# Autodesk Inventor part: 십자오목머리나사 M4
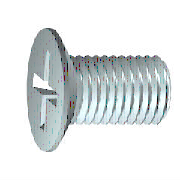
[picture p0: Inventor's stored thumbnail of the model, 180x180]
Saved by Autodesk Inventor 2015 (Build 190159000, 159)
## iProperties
IsCustomPart: 0
Created: 2012-02
Part Number: 십자오목머리나사 M4
Material: 강철, 연강
Description: 십자 오목 머리 나사
Document SubType Name: Modeling
Standard: KS B 1023
Designer: mduedu
Standards Organization: KS
Language: ko-KR
Size Designation: A  M 4 x 12 - H
Categories: <MemberInstance><Categories><Category DisplayName="조임쇠" InternalName="e4da775c-781d-43d5-af7c-5136215cf5a6" Mnemonic="FSTN"><Category DisplayName="볼트" InternalN
Density: 7.86 g/cm^3
Mass: 1.5048 g
Surface Area: 2.78557 cm^2
Volume: 0.191451 cm^3
Appearance: 주황색
Author: mduedu
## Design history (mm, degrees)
body "Solid1"
sketch "스케치1"
  geometry: L1 (2.6, 0)-(12, 0); L2 (12, 0)-(12, 2); L3 (12, 2)-(4.1, 2); L4 (4.1, 2)-(3.671, 1.785); L5 (3.671, 1.785)-(2.7, 1.785); L6 (0, 4.2)-(0, 2.4); L7 (0, 2.4)-(1.801, 1.502); L8 (1.801, 1.502)-(2.6, 0); L9 (-2.4, 0)-(14.4, 0) reference; L10 (0, -0.84)-(0, 5.04) reference; L11 (0, 4.2)-(0.285, 4.2); L12 (0.285, 4.2)-(2.7, 1.785); L13 (4.1, 2)-(2.485, 2)
  constraints: 22 end point, 3 parallel, 3 perpendicular, 2 collinear, 1 horizontal, 1 point on line
  dimensions: "d1" = 7.9 distance of L2.end L3.end (= GEL); "d2" = 4 diameter of L3 L1 (= GD); "d3" = 3.57058 diameter of L5 L1 (= BDM); "d4" = 4.8 diameter of L6.end L1 (= SDM); "d5" = 26.5 deg angle of L7 L1; "d6" = 62 deg angle of L8 L1; "d7" = 2.6 distance from line of L1.start L6 (= INTI); "d8" = 0.42941 horizontal distance of L4.end L3.end (= GAL); "d12" = 8.4 diameter of L11 L1 (= KOD); "d13" = 45 deg angle of L12 L1 (= 0.5 x SEWI); "d15" = 12 distance between parallel lines of L2 L6 (= NLG); "d24" = 2.7 distance from line of L5.end L6 (= KOH)
revolve "본체" stored, may be unused: angle "d16" = 90 deg
sketch "스케치2"
  geometry: L1 (0, 2.4)-(0, 0); L2 (0, 0)-(2.4, 0); L3 (0, 0)-(1.697, 1.697); L4 (0.312, 2.38)-(0.408, 0.734); L5 (2.38, 0.312)-(0.734, 0.408); L6 (0, -5.88)-(0, 5.88) reference; L7 (-5.88, 0)-(5.88, 0) reference; L8 (2.38, -0.312)-(0.734, -0.408); L9 (0.312, -2.38)-(0.408, -0.734); L10 (-0.312, -2.38)-(-0.408, -0.734); L11 (-2.38, -0.312)-(-0.734, -0.408); L12 (-2.38, 0.312)-(-0.734, 0.408); L13 (-0.312, 2.38)-(-0.408, 0.734); A1 r 0.72 centre (0, 0) between (0.72, 0) and (0, 0.72); A2 r 0.84 centre (0, 0) between (0.84, 0) and (0, 0.84); A3 r 2.4 centre (0, 0) between (2.38, 0.312) and (0.312, 2.38); A4 r 2.4 centre (0, 0) between (0.312, 2.38) and (0, 2.4); A5 r 2.4 centre (0, 0) between (2.4, 0) and (2.38, 0.312); A6 r 2.4 centre (0, 0) between (0, -2.4) and (0.312, -2.38); A7 r 2.4 centre (0, 0) between (0.312, -2.38) and (2.38, -0.312); A8 r 2.4 centre (0, 0) between (2.38, -0.312) and (2.4, 0); A9 r 2.4 centre (0, 0) between (0, 2.4) and (-0.312, 2.38); A10 r 2.4 centre (0, 0) between (-0.312, 2.38) and (-2.38, 0.312); A11 r 2.4 centre (0, 0) between (-2.38, 0.312) and (-2.4, 0); A12 r 2.4 centre (0, 0) between (-2.4, 0) and (-2.38, -0.312); A13 r 2.4 centre (0, 0) between (-2.38, -0.312) and (-0.312, -2.38); A14 r 2.4 centre (0, 0) between (-0.312, -2.38) and (0, -2.4); A15 r 0.347 centre (0.755, 0.755) between (0.408, 0.734) and (0.734, 0.408); A16 r 0.347 centre (0.755, -0.755) between (0.734, -0.408) and (0.408, -0.734); A17 r 0.347 centre (-0.755, -0.755) between (-0.408, -0.734) and (-0.734, -0.408); A18 r 0.347 centre (-0.755, 0.755) between (-0.734, 0.408) and (-0.408, 0.734); 3 further points
  constraints: 41 point on circle, 22 end point, 22 symmetric about line, 18 centre point, 11 coincident, 4 point on line, 3 tangent, 2 collinear, 1 perpendicular, 1 vertical, 19 other
  dimensions: "d17" = 1.44 diameter of A1 (= 0.3 x SDM); "d18" = 1.68 diameter of A2 (= 0.35 x SDM); "d19" = 4.8 diameter of A3 (= SDM); "d20" = 45 deg angle of L3 L2; "d21" = 0.3115 distance from line of L4.start L1 (= 0.5 x SBR)
extrude "슬롯" join sketch "스케치2" taper "d22" = 5 deg; stored distance "d79" = 25.4
fillet "모깎기1" dims "d23" = 0.1246 (= 0.2 x SBR)
feature "스레드" dims "d10" = 7.9 (= GEL), "d11" = 0
chamfer "모따기1" distance "d25" = 0.42941 (= -0.5 x SPD + 0.5 x GD); stored, may be unused: second distance "d26" = 0.21471 (= 0.5 x GAL), angle "d88" = 45 deg
workplane "Work Plane2"
other parameters: "NLG" = 12 [user parameter; used in 1 equation term], "GEL" = 7.9 [user parameter; used in 2 equation terms], "GAL" = 0.42941 (= 0.61345 x PTC) [user parameter; used in 3 equation terms], "SPD" = 3.14117 (= NND - 1.2269 x PTC) [user parameter; used in 1 equation term], "KOD" = 8.4 [user parameter; used in 1 equation term], "KOH" = 2.7 [user parameter; used in 1 equation term], "SBR" = 0.623 [user parameter; used in 2 equation terms], "INTI" = 2.6 [user parameter; used in 1 equation term], "SDM" = 4.8 [user parameter; used in 5 equation terms], "GD" = 4 (= NND) [user parameter; used in 2 equation terms], "BDM" = 3.57058 (= NND - GAL) [user parameter; used in 1 equation term], "SEWI" = 90 deg [user parameter; used in 1 equation term], "d9" = 4.8 (= SDM), "d27" = 0, "d91" = 0, "d92" = 0, "GUL" = 0.42941 (= 0.61345 x PTC) [user parameter], "TOA" = 30 deg [user parameter], "EPV" = 4.7 [user parameter], "THREADDIA" = 4 [user parameter; used in 1 equation term], "TPU" = 14.28571 (computed from PTC) [user parameter], "PTC" = 0.7 [user parameter; used in 5 equation terms], "NND" = 4 [user parameter; used in 3 equation terms], "GD1" = 3.14117 (= THREADDIA - 1.2269 x PTC) [user parameter]
